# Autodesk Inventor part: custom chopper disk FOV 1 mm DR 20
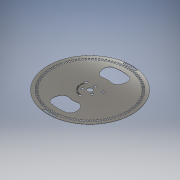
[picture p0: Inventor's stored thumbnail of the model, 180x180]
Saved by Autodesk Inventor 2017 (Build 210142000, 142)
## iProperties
Created: 2016-09
Part Number: custom chopper disk FOV 1 mm DR 20
Material: Generic
Document SubType Name: Modeling
Designer: Radek
Density: 1 g/cm^3
Appearance: Mirror
Author: Radek
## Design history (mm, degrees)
workplane "Work Plane1"
sketch "Sketch1"
  geometry: L1 (-46.781, 4.422)-(-44.253, 4.183) reference; L2 (-44.362, 2.791)-(-46.897, 2.951) reference; L3 (-46.411, 7.351)-(-43.903, 6.954) reference; L4 (-44.099, 5.571)-(-46.619, 5.889) reference; L5 (-45.858, 10.251)-(-43.38, 9.696) reference; L6 (-43.663, 8.329)-(-46.158, 8.805) reference; L7 (-45.124, 13.11)-(-42.685, 12.401) reference; L8 (-43.054, 11.054)-(-45.514, 11.686) reference; L9 (-44.212, 15.917)-(-41.822, 15.057) reference; L10 (-42.274, 13.736)-(-44.69, 14.521) reference; L11 (-43.125, 18.662)-(-40.794, 17.653) reference; L12 (-41.329, 16.363)-(-43.69, 17.298) reference; L13 (-41.868, 21.333)-(-39.605, 20.18) reference; L14 (-40.22, 18.926)-(-42.518, 20.007) reference; L15 (-40.446, 23.92)-(-38.26, 22.627) reference; L16 (-38.952, 21.414)-(-41.178, 22.638) reference; L17 (-38.865, 26.412)-(-36.764, 24.985) reference; L18 (-37.53, 23.818)-(-39.675, 25.179) reference; L19 (-37.129, 28.801)-(-35.122, 27.244) reference; L20 (-35.961, 26.127)-(-38.016, 27.62) reference; L21 (-35.248, 31.075)-(-33.342, 29.395) reference; L22 (-34.249, 28.333)-(-36.206, 29.953) reference; L23 (-33.227, 33.227)-(-31.431, 31.431) reference; L24 (-32.403, 30.428)-(-34.254, 32.167) reference; L25 (-31.075, 35.248)-(-29.395, 33.342) reference; L26 (-30.428, 32.403)-(-32.167, 34.254) reference; L27 (-28.801, 37.129)-(-27.244, 35.122) reference; L28 (-28.333, 34.249)-(-29.953, 36.206) reference; L29 (-26.412, 38.865)-(-24.985, 36.764) reference; L30 (-26.127, 35.961)-(-27.62, 38.016) reference; L31 (-23.92, 40.446)-(-22.627, 38.26) reference; L32 (-23.818, 37.53)-(-25.179, 39.675) reference; L33 (-21.333, 41.868)-(-20.18, 39.605) reference; L34 (-21.414, 38.952)-(-22.638, 41.178) reference; L35 (-18.662, 43.125)-(-17.653, 40.794) reference; L36 (-18.926, 40.22)-(-20.007, 42.518) reference; L37 (-15.917, 44.212)-(-15.057, 41.822) reference; L38 (-16.363, 41.329)-(-17.298, 43.69) reference; L39 (-13.11, 45.124)-(-12.401, 42.685) reference; L40 (-13.736, 42.274)-(-14.521, 44.69) reference; L41 (-10.251, 45.858)-(-9.696, 43.38) reference; L42 (-11.054, 43.054)-(-11.686, 45.514) reference; L43 (-7.351, 46.411)-(-6.954, 43.903) reference; L44 (-8.329, 43.663)-(-8.805, 46.158) reference; L45 (-4.422, 46.781)-(-4.183, 44.253) reference; L46 (-5.571, 44.099)-(-5.889, 46.619) reference; L47 (-1.476, 46.967)-(-1.396, 44.428) reference; L48 (-2.791, 44.362)-(-2.951, 46.897) reference; L49 (1.476, 46.967)-(1.396, 44.428) reference; L50 (0, 44.45)-(0, 46.99) reference; L51 (4.422, 46.781)-(4.183, 44.253) reference; L52 (2.791, 44.362)-(2.951, 46.897) reference; L53 (7.351, 46.411)-(6.954, 43.903) reference; L54 (5.571, 44.099)-(5.889, 46.619) reference; L55 (10.251, 45.858)-(9.696, 43.38) reference; L56 (8.329, 43.663)-(8.805, 46.158) reference; L57 (13.11, 45.124)-(12.401, 42.685) reference; L58 (11.054, 43.054)-(11.686, 45.514) reference; L59 (15.917, 44.212)-(15.057, 41.822) reference; L60 (13.736, 42.274)-(14.521, 44.69) reference; L61 (18.662, 43.125)-(17.653, 40.794) reference; L62 (16.363, 41.329)-(17.298, 43.69) reference; L63 (21.333, 41.868)-(20.18, 39.605) reference; L64 (18.926, 40.22)-(20.007, 42.518) reference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; C1 r 50.8 at (0, 0) reference; C2 r 2.984 at (0, 0) reference; C3 r 1.524 at (0, 6.553) reference; C4 r 1.524 at (10.339, 5.969) reference; C5 r 2.984 at (0, 0) reference; C6 r 1.524 at (0, -11.938) reference; C7 r 1.524 at (-5.675, -3.277) reference; C8 r 1.524 at (-10.339, 5.969) reference; C9 r 1.524 at (5.675, -3.277) reference; C10 r 50.8 at (0, 0) reference; C11 r 1.524 at (-5.675, -3.277) reference; C12 r 1.524 at (-10.339, 5.969) reference; C13 r 1.524 at (0, 6.553) reference; C14 r 1.524 at (10.339, 5.969) reference; C15 r 1.524 at (5.675, -3.277) reference; C16 r 1.524 at (0, -11.938) reference; C17 r 2.984 at (0, 0) reference; A1 r 17.081 centre (0, 0) between (0, -17.081) and (17.081, 0) reference; A2 r 17.081 centre (0, 0) between (0, 17.081) and (-17.081, 0) reference; A3 r 43.18 centre (0, 0) between (0, 43.18) and (-43.18, 0) reference; A4 r 43.18 centre (0, 0) between (0, -43.18) and (43.18, 0) reference; A5 r 44.45 centre (0, 0) between (-44.253, 4.183) and (-44.362, 2.791) reference; A6 r 46.99 centre (0, 0) between (-46.781, 4.422) and (-46.897, 2.951) reference; A7 r 44.45 centre (0, 0) between (-43.903, 6.954) and (-44.099, 5.571) reference; A8 r 46.99 centre (0, 0) between (-46.411, 7.351) and (-46.619, 5.889) reference; A9 r 44.45 centre (0, 0) between (-43.38, 9.696) and (-43.663, 8.329) reference; A10 r 46.99 centre (0, 0) between (-45.858, 10.251) and (-46.158, 8.805) reference; A11 r 44.45 centre (0, 0) between (-42.685, 12.401) and (-43.054, 11.054) reference; A12 r 46.99 centre (0, 0) between (-45.124, 13.11) and (-45.514, 11.686) reference; A13 r 44.45 centre (0, 0) between (-41.822, 15.057) and (-42.274, 13.736) reference; A14 r 46.99 centre (0, 0) between (-44.212, 15.917) and (-44.69, 14.521) reference; A15 r 44.45 centre (0, 0) between (-40.794, 17.653) and (-41.329, 16.363) reference; A16 r 46.99 centre (0, 0) between (-43.125, 18.662) and (-43.69, 17.298) reference; A17 r 44.45 centre (0, 0) between (-39.605, 20.18) and (-40.22, 18.926) reference; A18 r 46.99 centre (0, 0) between (-41.868, 21.333) and (-42.518, 20.007) reference; A19 r 44.45 centre (0, 0) between (-38.26, 22.627) and (-38.952, 21.414) reference; A20 r 46.99 centre (0, 0) between (-40.446, 23.92) and (-41.178, 22.638) reference; A21 r 44.45 centre (0, 0) between (-36.764, 24.985) and (-37.53, 23.818) reference; A22 r 46.99 centre (0, 0) between (-38.865, 26.412) and (-39.675, 25.179) reference; A23 r 44.45 centre (0, 0) between (-35.122, 27.244) and (-35.961, 26.127) reference; A24 r 46.99 centre (0, 0) between (-37.129, 28.801) and (-38.016, 27.62) reference; A25 r 44.45 centre (0, 0) between (-33.342, 29.395) and (-34.249, 28.333) reference; A26 r 46.99 centre (0, 0) between (-35.248, 31.075) and (-36.206, 29.953) reference; A27 r 44.45 centre (0, 0) between (-31.431, 31.431) and (-32.403, 30.428) reference; A28 r 46.99 centre (0, 0) between (-33.227, 33.227) and (-34.254, 32.167) reference; A29 r 44.45 centre (0, 0) between (-29.395, 33.342) and (-30.428, 32.403) reference; A30 r 46.99 centre (0, 0) between (-31.075, 35.248) and (-32.167, 34.254) reference; A31 r 44.45 centre (0, 0) between (-27.244, 35.122) and (-28.333, 34.249) reference; A32 r 46.99 centre (0, 0) between (-28.801, 37.129) and (-29.953, 36.206) reference; A33 r 44.45 centre (0, 0) between (-24.985, 36.764) and (-26.127, 35.961) reference; A34 r 46.99 centre (0, 0) between (-26.412, 38.865) and (-27.62, 38.016) reference; A35 r 44.45 centre (0, 0) between (-22.627, 38.26) and (-23.818, 37.53) reference; A36 r 46.99 centre (0, 0) between (-23.92, 40.446) and (-25.179, 39.675) reference; A37 r 44.45 centre (0, 0) between (-20.18, 39.605) and (-21.414, 38.952) reference; A38 r 46.99 centre (0, 0) between (-21.333, 41.868) and (-22.638, 41.178) reference; A39 r 44.45 centre (0, 0) between (-17.653, 40.794) and (-18.926, 40.22) reference; A40 r 46.99 centre (0, 0) between (-18.662, 43.125) and (-20.007, 42.518) reference; A41 r 44.45 centre (0, 0) between (-15.057, 41.822) and (-16.363, 41.329) reference; A42 r 46.99 centre (0, 0) between (-15.917, 44.212) and (-17.298, 43.69) reference; A43 r 44.45 centre (0, 0) between (-12.401, 42.685) and (-13.736, 42.274) reference; A44 r 46.99 centre (0, 0) between (-13.11, 45.124) and (-14.521, 44.69) reference; A45 r 44.45 centre (0, 0) between (-9.696, 43.38) and (-11.054, 43.054) reference; A46 r 46.99 centre (0, 0) between (-10.251, 45.858) and (-11.686, 45.514) reference; A47 r 44.45 centre (0, 0) between (-6.954, 43.903) and (-8.329, 43.663) reference; A48 r 46.99 centre (0, 0) between (-7.351, 46.411) and (-8.805, 46.158) reference; A49 r 44.45 centre (0, 0) between (-4.183, 44.253) and (-5.571, 44.099) reference; A50 r 46.99 centre (0, 0) between (-4.422, 46.781) and (-5.889, 46.619) reference; A51 r 44.45 centre (0, 0) between (-1.396, 44.428) and (-2.791, 44.362) reference; A52 r 46.99 centre (0, 0) between (-1.476, 46.967) and (-2.951, 46.897) reference; A53 r 44.45 centre (0, 0) between (1.396, 44.428) and (0, 44.45) reference; A54 r 46.99 centre (0, 0) between (1.476, 46.967) and (0, 46.99) reference; A55 r 44.45 centre (0, 0) between (4.183, 44.253) and (2.791, 44.362) reference; A56 r 46.99 centre (0, 0) between (4.422, 46.781) and (2.951, 46.897) reference; A57 r 44.45 centre (0, 0) between (6.954, 43.903) and (5.571, 44.099) reference; A58 r 46.99 centre (0, 0) between (7.351, 46.411) and (5.889, 46.619) reference; A59 r 44.45 centre (0, 0) between (9.696, 43.38) and (8.329, 43.663) reference; A60 r 46.99 centre (0, 0) between (10.251, 45.858) and (8.805, 46.158) reference; A61 r 44.45 centre (0, 0) between (12.401, 42.685) and (11.054, 43.054) reference; A62 r 46.99 centre (0, 0) between (13.11, 45.124) and (11.686, 45.514) reference; A63 r 44.45 centre (0, 0) between (15.057, 41.822) and (13.736, 42.274) reference; A64 r 46.99 centre (0, 0) between (15.917, 44.212) and (14.521, 44.69) reference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; 1 further point
  constraints: 8 end point, 2 collinear, 1 parallel
extrude "Extrusion2" new body sketch "Sketch1" distance "d2" = 0.254; taper "d3" = 0 deg
sketch "Sketch2"
  geometry: L1 (-46.781, 4.422)-(-44.253, 4.183) reference; L2 (-44.362, 2.791)-(-46.897, 2.951) reference; L3 (-46.411, 7.351)-(-43.903, 6.954) reference; L4 (-44.099, 5.571)-(-46.619, 5.889) reference; L5 (-45.858, 10.251)-(-43.38, 9.696) reference; L6 (-43.663, 8.329)-(-46.158, 8.805) reference; L7 (-45.124, 13.11)-(-42.685, 12.401) reference; L8 (-43.054, 11.054)-(-45.514, 11.686) reference; L9 (-44.212, 15.917)-(-41.822, 15.057) reference; L10 (-42.274, 13.736)-(-44.69, 14.521) reference; L11 (-43.125, 18.662)-(-40.794, 17.653) reference; L12 (-41.329, 16.363)-(-43.69, 17.298) reference; L13 (-41.868, 21.333)-(-39.605, 20.18) reference; L14 (-40.22, 18.926)-(-42.518, 20.007) reference; L15 (-40.446, 23.92)-(-38.26, 22.627) reference; L16 (-38.952, 21.414)-(-41.178, 22.638) reference; L17 (-38.865, 26.412)-(-36.764, 24.985) reference; L18 (-37.53, 23.818)-(-39.675, 25.179) reference; L19 (-37.129, 28.801)-(-35.122, 27.244) reference; L20 (-35.961, 26.127)-(-38.016, 27.62) reference; L21 (-35.248, 31.075)-(-33.342, 29.395) reference; L22 (-34.249, 28.333)-(-36.206, 29.953) reference; L23 (-33.227, 33.227)-(-31.431, 31.431) reference; L24 (-32.403, 30.428)-(-34.254, 32.167) reference; L25 (-31.075, 35.248)-(-29.395, 33.342) reference; L26 (-30.428, 32.403)-(-32.167, 34.254) reference; L27 (-28.801, 37.129)-(-27.244, 35.122) reference; L28 (-28.333, 34.249)-(-29.953, 36.206) reference; L29 (-26.412, 38.865)-(-24.985, 36.764) reference; L30 (-26.127, 35.961)-(-27.62, 38.016) reference; L31 (-23.92, 40.446)-(-22.627, 38.26) reference; L32 (-23.818, 37.53)-(-25.179, 39.675) reference; L33 (-21.333, 41.868)-(-20.18, 39.605) reference; L34 (-21.414, 38.952)-(-22.638, 41.178) reference; L35 (-18.662, 43.125)-(-17.653, 40.794) reference; L36 (-18.926, 40.22)-(-20.007, 42.518) reference; L37 (-15.917, 44.212)-(-15.057, 41.822) reference; L38 (-16.363, 41.329)-(-17.298, 43.69) reference; L39 (-13.11, 45.124)-(-12.401, 42.685) reference; L40 (-13.736, 42.274)-(-14.521, 44.69) reference; L41 (-10.251, 45.858)-(-9.696, 43.38) reference; L42 (-11.054, 43.054)-(-11.686, 45.514) reference; L43 (-7.351, 46.411)-(-6.954, 43.903) reference; L44 (-8.329, 43.663)-(-8.805, 46.158) reference; L45 (-4.422, 46.781)-(-4.183, 44.253) reference; L46 (-5.571, 44.099)-(-5.889, 46.619) reference; L47 (-1.476, 46.967)-(-1.396, 44.428) reference; L48 (-2.791, 44.362)-(-2.951, 46.897) reference; L49 (1.476, 46.967)-(1.396, 44.428) reference; L50 (0, 44.45)-(0, 46.99) reference; L51 (4.422, 46.781)-(4.183, 44.253) reference; L52 (2.791, 44.362)-(2.951, 46.897) reference; L53 (7.351, 46.411)-(6.954, 43.903) reference; L54 (5.571, 44.099)-(5.889, 46.619) reference; L55 (10.251, 45.858)-(9.696, 43.38) reference; L56 (8.329, 43.663)-(8.805, 46.158) reference; L57 (13.11, 45.124)-(12.401, 42.685) reference; L58 (11.054, 43.054)-(11.686, 45.514) reference; L59 (15.917, 44.212)-(15.057, 41.822) reference; L60 (13.736, 42.274)-(14.521, 44.69) reference; L61 (18.662, 43.125)-(17.653, 40.794) reference; L62 (16.363, 41.329)-(17.298, 43.69) reference; L63 (21.333, 41.868)-(20.18, 39.605) reference; L64 (18.926, 40.22)-(20.007, 42.518) reference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; C1 r 50.8 at (0, 0) reference; C2 r 1.524 at (-5.675, -3.277) reference; C3 r 1.524 at (-10.339, 5.969) reference; C4 r 1.524 at (0, 6.553) reference; C5 r 1.524 at (10.339, 5.969) reference; C6 r 1.524 at (5.675, -3.277) reference; C7 r 1.524 at (0, -11.938) reference; C8 r 2.984 at (0, 0) reference; A1 r 44.45 centre (0, 0) between (-44.253, 4.183) and (-44.362, 2.791) reference; A2 r 46.99 centre (0, 0) between (-46.781, 4.422) and (-46.897, 2.951) reference; A3 r 44.45 centre (0, 0) between (-43.903, 6.954) and (-44.099, 5.571) reference; A4 r 46.99 centre (0, 0) between (-46.411, 7.351) and (-46.619, 5.889) reference; A5 r 44.45 centre (0, 0) between (-43.38, 9.696) and (-43.663, 8.329) reference; A6 r 46.99 centre (0, 0) between (-45.858, 10.251) and (-46.158, 8.805) reference; A7 r 44.45 centre (0, 0) between (-42.685, 12.401) and (-43.054, 11.054) reference; A8 r 46.99 centre (0, 0) between (-45.124, 13.11) and (-45.514, 11.686) reference; A9 r 44.45 centre (0, 0) between (-41.822, 15.057) and (-42.274, 13.736) reference; A10 r 46.99 centre (0, 0) between (-44.212, 15.917) and (-44.69, 14.521) reference; A11 r 44.45 centre (0, 0) between (-40.794, 17.653) and (-41.329, 16.363) reference; A12 r 46.99 centre (0, 0) between (-43.125, 18.662) and (-43.69, 17.298) reference; A13 r 44.45 centre (0, 0) between (-39.605, 20.18) and (-40.22, 18.926) reference; A14 r 46.99 centre (0, 0) between (-41.868, 21.333) and (-42.518, 20.007) reference; A15 r 44.45 centre (0, 0) between (-38.26, 22.627) and (-38.952, 21.414) reference; A16 r 46.99 centre (0, 0) between (-40.446, 23.92) and (-41.178, 22.638) reference; A17 r 44.45 centre (0, 0) between (-36.764, 24.985) and (-37.53, 23.818) reference; A18 r 46.99 centre (0, 0) between (-38.865, 26.412) and (-39.675, 25.179) reference; A19 r 44.45 centre (0, 0) between (-35.122, 27.244) and (-35.961, 26.127) reference; A20 r 46.99 centre (0, 0) between (-37.129, 28.801) and (-38.016, 27.62) reference; A21 r 44.45 centre (0, 0) between (-33.342, 29.395) and (-34.249, 28.333) reference; A22 r 46.99 centre (0, 0) between (-35.248, 31.075) and (-36.206, 29.953) reference; A23 r 44.45 centre (0, 0) between (-31.431, 31.431) and (-32.403, 30.428) reference; A24 r 46.99 centre (0, 0) between (-33.227, 33.227) and (-34.254, 32.167) reference; A25 r 44.45 centre (0, 0) between (-29.395, 33.342) and (-30.428, 32.403) reference; A26 r 46.99 centre (0, 0) between (-31.075, 35.248) and (-32.167, 34.254) reference; A27 r 44.45 centre (0, 0) between (-27.244, 35.122) and (-28.333, 34.249) reference; A28 r 46.99 centre (0, 0) between (-28.801, 37.129) and (-29.953, 36.206) reference; A29 r 44.45 centre (0, 0) between (-24.985, 36.764) and (-26.127, 35.961) reference; A30 r 46.99 centre (0, 0) between (-26.412, 38.865) and (-27.62, 38.016) reference; A31 r 44.45 centre (0, 0) between (-22.627, 38.26) and (-23.818, 37.53) reference; A32 r 46.99 centre (0, 0) between (-23.92, 40.446) and (-25.179, 39.675) reference; A33 r 44.45 centre (0, 0) between (-20.18, 39.605) and (-21.414, 38.952) reference; A34 r 46.99 centre (0, 0) between (-21.333, 41.868) and (-22.638, 41.178) reference; A35 r 44.45 centre (0, 0) between (-17.653, 40.794) and (-18.926, 40.22) reference; A36 r 46.99 centre (0, 0) between (-18.662, 43.125) and (-20.007, 42.518) reference; A37 r 44.45 centre (0, 0) between (-15.057, 41.822) and (-16.363, 41.329) reference; A38 r 46.99 centre (0, 0) between (-15.917, 44.212) and (-17.298, 43.69) reference; A39 r 44.45 centre (0, 0) between (-12.401, 42.685) and (-13.736, 42.274) reference; A40 r 46.99 centre (0, 0) between (-13.11, 45.124) and (-14.521, 44.69) reference; A41 r 44.45 centre (0, 0) between (-9.696, 43.38) and (-11.054, 43.054) reference; A42 r 46.99 centre (0, 0) between (-10.251, 45.858) and (-11.686, 45.514) reference; A43 r 44.45 centre (0, 0) between (-6.954, 43.903) and (-8.329, 43.663) reference; A44 r 46.99 centre (0, 0) between (-7.351, 46.411) and (-8.805, 46.158) reference; A45 r 44.45 centre (0, 0) between (-4.183, 44.253) and (-5.571, 44.099) reference; A46 r 46.99 centre (0, 0) between (-4.422, 46.781) and (-5.889, 46.619) reference; A47 r 44.45 centre (0, 0) between (-1.396, 44.428) and (-2.791, 44.362) reference; A48 r 46.99 centre (0, 0) between (-1.476, 46.967) and (-2.951, 46.897) reference; A49 r 44.45 centre (0, 0) between (1.396, 44.428) and (0, 44.45) reference; A50 r 46.99 centre (0, 0) between (1.476, 46.967) and (0, 46.99) reference; A51 r 44.45 centre (0, 0) between (4.183, 44.253) and (2.791, 44.362) reference; A52 r 46.99 centre (0, 0) between (4.422, 46.781) and (2.951, 46.897) reference; A53 r 44.45 centre (0, 0) between (6.954, 43.903) and (5.571, 44.099) reference; A54 r 46.99 centre (0, 0) between (7.351, 46.411) and (5.889, 46.619) reference; A55 r 44.45 centre (0, 0) between (9.696, 43.38) and (8.329, 43.663) reference; A56 r 46.99 centre (0, 0) between (10.251, 45.858) and (8.805, 46.158) reference; A57 r 44.45 centre (0, 0) between (12.401, 42.685) and (11.054, 43.054) reference; A58 r 46.99 centre (0, 0) between (13.11, 45.124) and (11.686, 45.514) reference; A59 r 44.45 centre (0, 0) between (15.057, 41.822) and (13.736, 42.274) reference; A60 r 46.99 centre (0, 0) between (15.917, 44.212) and (14.521, 44.69) reference; A61 r 44.45 centre (0, 0) between (17.653, 40.794) and (16.363, 41.329) reference; A62 r 46.99 centre (0, 0) between (18.662, 43.125) and (17.298, 43.69) reference; A63 r 44.45 centre (0, 0) between (20.18, 39.605) and (18.926, 40.22) reference; A64 r 46.99 centre (0, 0) between (21.333, 41.868) and (20.007, 42.518) reference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; 1 further point
  constraints: 8 end point, 1 collinear
extrude "Extrusion3" cut sketch "Sketch2" stored distance "d4" = 0.254; taper "d5" = 0 deg
sketch "Sketch3" dims "d20" = 6.21111 (= 0.5 x holediameter), "d21" = 8.78384 (= 1.41421 x d20)
  geometry: L1 (-10.339, 5.969)-(10.339, 5.969); L2 (0, 0)-(50.8, 0); L3 (0, 44.45)-(0, 46.99) reference; L4 (0, 0)-(0, 50.8); L5 (0, 30)-(0, 21.216); L6 (0, 50.165)-(0, 48.26) reference; L7 (-48.26, 0)-(-50.165, 0) reference; L8 (0, 0)-(-0.683, -14.045); L9 (0, 50.8)-(0, 50.165); L10 (5.491, 20.493)-(10.243, 37.402); L11 (-5.491, 20.493)-(-10.243, 37.402); C1 r 2.984 at (0, 0) reference; C2 r 15.25 at (0, 0); C3 r 1.524 at (-10.339, 5.969) reference; C4 r 1.524 at (0, -11.938) reference; C5 r 1.524 at (10.339, 5.969) reference; C6 r 1.524 at (-5.675, -3.277) reference; C7 r 1.524 at (5.675, -3.277) reference; A1 r 50.8 centre (0, 0) between (50.8, 0) and (0, 50.8) reference; A2 r 48.26 centre (0, 0) between (0, 48.26) and (-48.26, 0) reference; A3 r 50.165 centre (0, 0) between (0, 50.165) and (-50.165, 0) reference; A4 r 50.165 centre (0, 0) between (-20.154, -45.939) and (22.037, -45.066); A5 r 48.26 centre (0, 0) between (-19.033, -44.348) and (20.956, -43.472); 3 further points; 3 other entities
  constraints: 16 end point, 8 point on circle, 3 centre point, 3 coincident, 2 vertical, 1 collinear, 1 horizontal, 1 parallel, 1 point on line, 1 vertical alignment, 19 other
  dimensions: "d9" = 30.5 diameter of C2; "d18" = 0 distance between parallel lines of L4 L5; "d19" = 30 distance of point (0, 0) L5.start (= offaxis); "d24" = 15 deg dimension on point (0, 0) L5.start point (-7.765, 28.978) (= 0.5 x angle); "d28" = 15 deg dimension on point (0, 0) point (7.765, 28.978) L5.start (= 0.5 x angle); "d32" = 0.635 distance of L4.end L6.start (derived)
extrude "Extrusion7" cut sketch "Sketch3" stored distance "d40" = 10; taper "d41" = 0 deg
sketch "Sketch4"
  geometry: L1 (-10.243, 37.402)-(-5.491, 20.493) reference; L2 (5.491, 20.493)-(10.243, 37.402) reference; L3 (10.243, 37.402)-(5.491, 20.493) reference; L4 (-5.491, 20.493)-(-10.243, 37.402) reference; L5 (-5.491, 20.493)-(-10.243, 37.402); L6 (5.491, 20.493)-(10.243, 37.402); C1 r 2.984 at (0, 0) reference; C2 r 50.8 at (0, 0) reference; A1 r 21.216 centre (0, 0) between (5.491, 20.493) and (-5.491, 20.493); A2 r 38.779 centre (0, 0) between (10.243, 37.402) and (-10.243, 37.402); 3 further points; 2 other entities
  constraints: 4 end point, 4 point on circle, 2 centre point, 2 coincident, 2 collinear, 2 other
extrude "Extrusion8" cut sketch "Sketch4" stored distance "d42" = 10; taper "d43" = 0 deg
sketch "Sketch5"
  geometry: L1 (0, 0)-(-7.947, 50.175); L2 (0, 0)-(7.947, 50.175); L3 (7.524, 47.508)-(7.837, 49.483); L4 (-7.524, 47.508)-(-7.837, 49.483); L5 (6.954, 43.903)-(7.351, 46.411) reference; L6 (4.422, 46.781)-(4.183, 44.253) reference; L7 (7.351, 46.411)-(6.954, 43.903) reference; C1 r 2.984 at (0, 0) reference; A1 r 50.8 centre (0, 0) between (-7.947, 50.175) and (7.947, 50.175) reference; A2 r 21.216 centre (0, 0) between (5.491, 20.493) and (-5.491, 20.493) reference; A3 r 38.779 centre (0, 0) between (10.243, 37.402) and (-10.243, 37.402) reference; A4 r 48.1 centre (0, 0) between (7.524, 47.508) and (-7.524, 47.508); A5 r 50.1 centre (0, 0) between (7.837, 49.483) and (-7.837, 49.483); 4 further points; 2 other entities
  constraints: 8 end point, 6 point on circle, 3 point on line, 2 centre point, 2 coincident, 2 collinear, 1 midpoint, 8 other
  dimensions: "d44" = 0.7 radial gap between concentric circles of A1 A5; "d45" = 2 radial gap between concentric circles of A5 A4; "d53" = 18 deg angle of L1 L2
extrude "Extrusion9" cut sketch "Sketch5" stored distance "d46" = 10; taper "d47" = 0 deg
pattern_circular "Circular Pattern3" dims angle "d49" = 360 deg
sketch "Sketch6"
  geometry: L1 (21.216, 0)-(20.493, 0) reference; L2 (37.402, 0)-(38.779, 0) reference; L3 (20.493, -0.254)-(21.216, -0.254) reference; L4 (38.779, -0.254)-(37.402, -0.254) reference; L5 (-50.8, 0)-(50.8, 0) reference; L6 (-50.8, -0.254)-(50.8, -0.254) reference; L7 (21.216, 0)-(38.779, 0); L8 (21.216, -0.254)-(38.779, -0.254); L9 (29.998, -0.254)-(29.998, 0); L10 (29.998, -0.127)-(32.933, -3.062); 1 further point
  constraints: 8 end point, 3 midpoint, 1 collinear, 1 parallel
  dimensions: "d51" = 135 deg angle of L10 L9
workaxis "Work Axis1"
workplane "Work Plane3"
  workplane "Work Plane2"
sketch "Sketch7"
  geometry: L1 (0, -11.938)-(-10.339, 5.969); C1 r 1.524 at (0, -11.938) reference; C2 r 1.524 at (-10.339, 5.969) reference; C3 r 2.984 at (0, 0) reference; C4 r 10.414 at (0, 0); 2 further points
  constraints: 2 end point, 1 centre point, 1 coincident, 1 tangent, 1 other
extrude "Extrusion11" cut sketch "Sketch7" stored distance "d57" = 10; taper "d58" = 0 deg
body "Solid2"
pattern_circular "Circular Pattern1" dims angle "d7" = 360 deg
node "Reference1"
node "Reference2"
node "Reference3"
node "Reference4"
node "Reference5"
node "Reference6"
node "Reference7"
node "Reference8"
node "Reference9"
node "Reference10"
node "Reference11"
node "Reference12"
node "Reference13"
node "Reference14"
node "Reference15"
node "Reference16"
node "Reference17"
node "Reference18"
node "Reference19"
other parameters: "d12" = 6.61111 (computed from ftube, FOV), "FOV" = 1 [user parameter; used in 2 equation terms], "dutycycle" = 2.98471 (computed from holelength, offaxis) [user parameter], "offaxis" = 30 [user parameter; used in 4 equation terms], "angle" = 30 deg (computed from holediameter, holelength, offaxis) [user parameter; used in 2 equation terms], "holelength" = 28.13019 (computed from dutyratio, offaxis, holediameter) [user parameter; used in 2 equation terms], "holediameter" = 12.42222 (computed from FOV, ftube) [user parameter; used in 3 equation terms], "dutyratio" = 2 [user parameter; used in 1 equation term], "d52" = 45 deg
